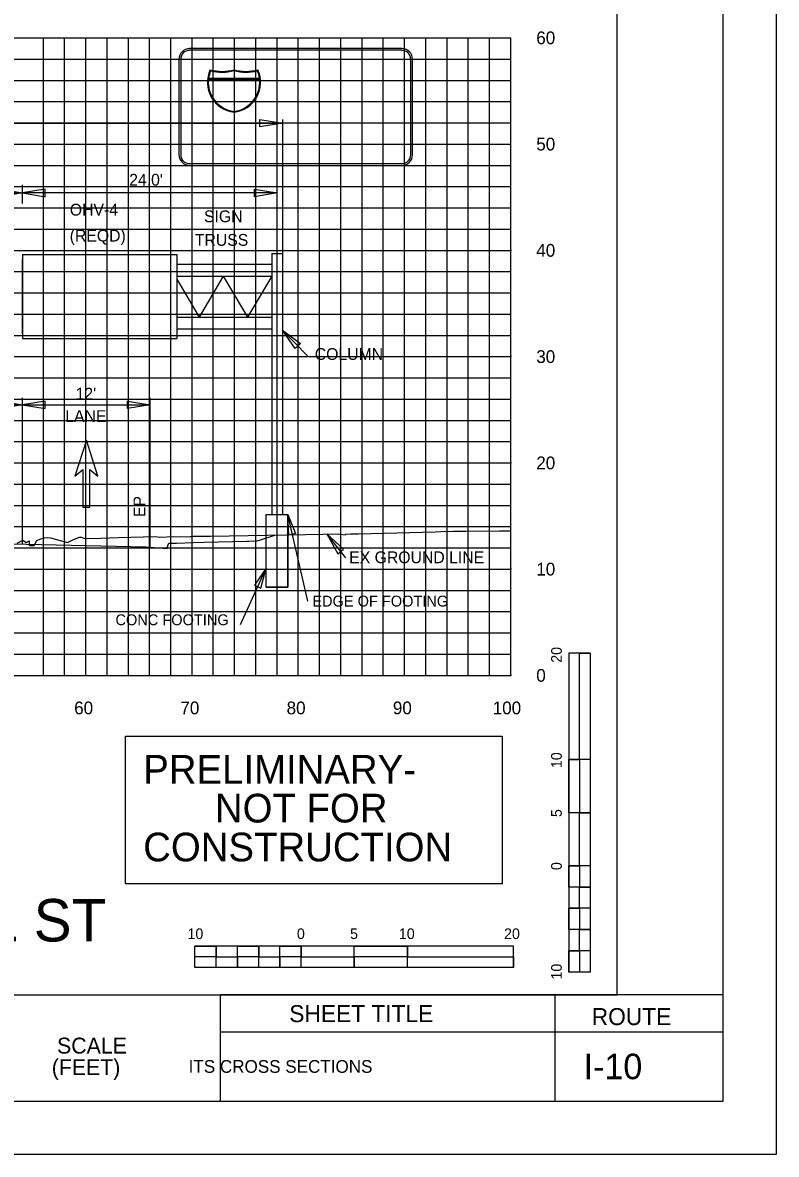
# Model space of a CAD drawing. Extents: x 2193008 to 2198143, y 1236112 to 1237864.
# Drawn here: x 2194781.7 to 2194852.7, y 1237118 to 1237224.5 of the extents above; entities that cross this region are included whole.
import ezdxf

# ---------------------------------------------------------------- set-up
doc = ezdxf.new("R2010")
doc.units = 0
for name, color, linetype in [('1', 7, 'Continuous'), ('10', 7, 'Continuous'), ('3', 7, 'Continuous'), ('31', 7, 'Continuous'), ('60', 7, 'Continuous'), ('ANNO-SHT', 7, 'Continuous'), ('ANNO-SYMB', 7, 'Continuous'), ('ANNO-TXT', 7, 'Continuous'), ('CL-CNST', 7, 'Continuous'), ('GSCOLORFILL', 7, 'Continuous'), ('GSDIMS', 7, 'Continuous'), ('GSOUTLINE', 7, 'Continuous'), ('Level 1', 7, 'Continuous'), ('Level 28', 7, 'Continuous'), ('Level 33', 7, 'Continuous'), ('Level 55', 7, 'Continuous'), ('Level 6', 7, 'Continuous'), ('Level 62', 7, 'Continuous'), ('M-ROADS', 7, 'Continuous'), ('SHT-BDR', 7, 'Continuous'), ('SHT-BNDRY', 7, 'Continuous'), ('V7Level1', 7, 'Continuous')]:
    doc.layers.add(name, color=color, linetype=linetype)

msp = doc.modelspace()

# ---------------------------------------------------------------- linework, layer by layer
msp.add_line((2194805.69, 1237202.24), (2194805.69, 1237208.86))
at = {"layer": '1'}
msp.add_lwpolyline([(2194791.41, 1237157.4), (2194826.87, 1237157.4), (2194826.87, 1237143.51), (2194791.41, 1237143.51)], close=True, dxfattribs=at)
at = {"layer": '3'}
for p, q in [((2194736.69, 1237215.09), (2194806.19, 1237215.09)), ((2194806.19, 1237215.44), (2194806.19, 1237202.8)), ((2194805.19, 1237202.8), (2194805.19, 1237178.26)), ((2194806.19, 1237202.8), (2194806.19, 1237178.26)), ((2194808.56, 1237193.17), (2194806.19, 1237195.61)), ((2194781.74, 1237175.47), (2194781.74, 1237189.23)), ((2194793.74, 1237175.2), (2194793.74, 1237189.23)), ((2194804.66, 1237178.26), (2194806.69, 1237178.26)), ((2194804.66, 1237171.41), (2194804.66, 1237178.26)), ((2194806.69, 1237171.41), (2194806.69, 1237178.26)), ((2194808.58, 1237170.1), (2194806.69, 1237178.26)), ((2194812.15, 1237174.16), (2194810.38, 1237176.42)), ((2194802.24, 1237167.9), (2194804.66, 1237173.2)), ((2194804.66, 1237171.41), (2194806.69, 1237171.41))]:
    msp.add_line(p, q, dxfattribs=at)
at = {"layer": '60'}
for p, q in [((2194827.69, 1237163.11), (2194827.69, 1237223.11)), ((2194827.75, 1237203.11), (2194827.69, 1237203.11)), ((2194827.75, 1237193.11), (2194827.69, 1237193.11)), ((2194827.75, 1237183.11), (2194827.69, 1237183.11)), ((2194827.75, 1237173.11), (2194827.69, 1237173.11)), ((2194697.69, 1237163.11), (2194827.69, 1237163.11)), ((2194787.69, 1237163.05), (2194787.69, 1237163.11)), ((2194797.69, 1237163.05), (2194797.69, 1237163.11)), ((2194807.69, 1237163.05), (2194807.69, 1237163.11)), ((2194817.69, 1237163.05), (2194817.69, 1237163.11)), ((2194827.69, 1237163.05), (2194827.69, 1237163.11)), ((2194827.75, 1237163.11), (2194827.69, 1237163.11))]:
    msp.add_line(p, q, dxfattribs=at)
at = {"layer": 'ANNO-TXT'}
for p, q in [((2194800.35, 1237129.57), (2194831.88, 1237129.57)), ((2194831.88, 1237129.57), (2194847.69, 1237129.57))]:
    msp.add_line(p, q, dxfattribs=at)
at = {"layer": 'CL-CNST'}
msp.add_lwpolyline([(2194755.3, 1237176.05), (2194793.33, 1237175.21), (2194793.73, 1237175.18), (2194795.33, 1237175.05), (2194795.36, 1237175.15), (2194795.5, 1237175.55), (2194795.56, 1237175.55), (2194795.83, 1237175.55), (2194796.23, 1237175.56), (2194797.83, 1237175.63), (2194798.83, 1237175.65), (2194802.83, 1237175.73), (2194803.03, 1237175.73), (2194803.83, 1237175.77), (2194804.12, 1237175.87), (2194805.49, 1237176.32)], dxfattribs=at)
at = {"layer": 'GSCOLORFILL'}
msp.add_line((2194781.74, 1237195.26), (2194781.74, 1237202.25), dxfattribs=at)
at = {"layer": 'GSDIMS'}
for p, q in [((2194769.25, 1237208.51), (2194781.74, 1237208.51)), ((2194781.74, 1237207.53), (2194781.74, 1237209.27)), ((2194805.69, 1237208.51), (2194781.74, 1237208.51)), ((2194781.74, 1237202.71), (2194796.25, 1237202.71)), ((2194781.74, 1237202.71), (2194781.74, 1237194.8)), ((2194796.25, 1237202.71), (2194796.25, 1237194.8)), ((2194805.19, 1237202.8), (2194806.19, 1237202.8)), ((2194796.25, 1237201.8), (2194805.19, 1237201.8)), ((2194796.25, 1237200.69), (2194805.19, 1237200.69)), ((2194796.25, 1237200.39), (2194798.35, 1237196.82)), ((2194800.63, 1237200.69), (2194798.35, 1237196.82)), ((2194800.63, 1237200.69), (2194802.91, 1237196.82)), ((2194805.19, 1237200.69), (2194802.91, 1237196.82)), ((2194796.25, 1237196.82), (2194805.19, 1237196.82)), ((2194796.25, 1237195.71), (2194805.19, 1237195.71)), ((2194781.74, 1237194.8), (2194796.25, 1237194.8)), ((2194769.74, 1237188.57), (2194781.74, 1237188.57)), ((2194781.74, 1237188.57), (2194793.74, 1237188.57))]:
    msp.add_line(p, q, dxfattribs=at)
for points in [[(2194806.19, 1237215.09), (2194804.06, 1237214.75), (2194804.06, 1237215.44)], [(2194781.74, 1237208.51), (2194779.61, 1237208.16), (2194779.61, 1237208.86)], [(2194781.74, 1237208.51), (2194783.87, 1237208.16), (2194783.87, 1237208.86)], [(2194805.69, 1237208.51), (2194803.56, 1237208.16), (2194803.56, 1237208.86)], [(2194806.19, 1237195.61), (2194807.91, 1237194.34), (2194807.4, 1237193.86)], [(2194781.74, 1237188.57), (2194779.61, 1237188.22), (2194779.61, 1237188.91)], [(2194781.74, 1237188.57), (2194783.87, 1237188.22), (2194783.87, 1237188.91)], [(2194793.74, 1237188.57), (2194791.61, 1237188.22), (2194791.61, 1237188.91)], [(2194806.69, 1237178.26), (2194807.43, 1237176.46), (2194806.81, 1237176.32)], [(2194810.38, 1237176.42), (2194811.41, 1237174.54), (2194811.95, 1237174.98)], [(2194804.66, 1237173.2), (2194803.57, 1237171.59), (2194804.16, 1237171.32)]]:
    msp.add_lwpolyline(points, close=True, dxfattribs=at)
at = {"layer": 'GSOUTLINE'}
for p, q in [((2194817.44, 1237222.1), (2194797.45, 1237222.1)), ((2194817.44, 1237221.94), (2194797.45, 1237221.94)), ((2194796.45, 1237221.1), (2194796.45, 1237212.11)), ((2194796.62, 1237221.1), (2194796.62, 1237212.11)), ((2194818.28, 1237212.11), (2194818.28, 1237221.1)), ((2194818.44, 1237212.11), (2194818.44, 1237221.1)), ((2194797.45, 1237211.28), (2194817.44, 1237211.28)), ((2194797.45, 1237211.11), (2194817.44, 1237211.11))]:
    msp.add_line(p, q, dxfattribs=at)
for points in [[(2194799.24, 1237219.19), (2194804.04, 1237219.19)], [(2194804.03, 1237219.28), (2194799.25, 1237219.28)]]:
    msp.add_lwpolyline(points, dxfattribs=at)
for centre, major_axis, start_param, end_param in [((2194797.45, 1237221.1), (1, 0), 1.570796, 3.141593), ((2194797.45, 1237221.1), (0.833, 0), 1.570796, 3.141593), ((2194817.44, 1237221.1), (1, 0), 0, 1.570796), ((2194817.44, 1237221.1), (0.833, 0), 0, 1.570796), ((2194801.97, 1237218.92), (2.83, 0), 2.709569, 4.594469), ((2194800.52, 1237223.95), (4, 0), 4.428637, 4.996141), ((2194802.76, 1237223.95), (4, 0), 4.428637, 4.996141), ((2194801.31, 1237218.92), (2.83, 0), 4.830309, 6.715209), ((2194801.97, 1237218.92), (2.75, 0), 3.043371, 4.590878), ((2194801.97, 1237218.92), (2.75, 0), 2.735396, 3.01287), ((2194800.52, 1237223.95), (4.08, 0), 4.446475, 4.990194), ((2194802.76, 1237223.95), (4.08, 0), 4.434584, 4.978303), ((2194801.31, 1237218.92), (2.75, 0), 4.8339, 6.381407), ((2194801.31, 1237218.92), (2.75, 0), 0.128722, 0.406196), ((2194797.45, 1237212.11), (1, 0), 3.141593, 4.712389), ((2194797.45, 1237212.11), (0.833, 0), 3.141593, 4.712389), ((2194817.44, 1237212.11), (1, 0), 4.712389, 6.283185), ((2194817.44, 1237212.11), (0.833, 0), 4.712389, 6.283185)]:
    msp.add_ellipse(centre, major_axis=major_axis, ratio=0.999829, start_param=start_param, end_param=end_param, dxfattribs=at)
at = {"layer": 'Level 1'}
for p, q in [((2194833.16, 1237165.19), (2194833.16, 1237135.19)), ((2194835.16, 1237165.19), (2194833.16, 1237165.19)), ((2194835.16, 1237165.19), (2194835.16, 1237155.19)), ((2194835.16, 1237165.19), (2194835.16, 1237135.19)), ((2194834.16, 1237155.19), (2194833.16, 1237155.19)), ((2194835.16, 1237155.19), (2194833.16, 1237155.19)), ((2194834.16, 1237155.19), (2194834.16, 1237150.19)), ((2194835.16, 1237150.19), (2194833.16, 1237150.19)), ((2194835.16, 1237150.19), (2194834.16, 1237150.19)), ((2194835.16, 1237150.19), (2194835.16, 1237145.19)), ((2194834.16, 1237145.19), (2194833.16, 1237145.19)), ((2194835.16, 1237145.19), (2194833.16, 1237145.19)), ((2194834.16, 1237145.19), (2194834.16, 1237143.19)), ((2194835.16, 1237143.19), (2194834.16, 1237143.19)), ((2194835.16, 1237143.19), (2194835.16, 1237141.19)), ((2194834.16, 1237141.19), (2194833.16, 1237141.19)), ((2194834.16, 1237141.19), (2194834.16, 1237139.19)), ((2194835.16, 1237139.19), (2194834.16, 1237139.19)), ((2194835.16, 1237139.19), (2194835.16, 1237137.19)), ((2194827.96, 1237137.63), (2194797.96, 1237137.63)), ((2194797.96, 1237135.63), (2194797.96, 1237137.63)), ((2194799.96, 1237136.63), (2194799.96, 1237137.63)), ((2194803.96, 1237136.63), (2194803.96, 1237137.63)), ((2194807.96, 1237136.63), (2194807.96, 1237137.63)), ((2194807.96, 1237135.63), (2194807.96, 1237137.63)), ((2194812.96, 1237135.63), (2194812.96, 1237137.63)), ((2194817.96, 1237136.63), (2194817.96, 1237137.63)), ((2194817.96, 1237135.63), (2194817.96, 1237137.63)), ((2194827.96, 1237135.63), (2194827.96, 1237137.63)), ((2194834.16, 1237137.19), (2194833.16, 1237137.19)), ((2194834.16, 1237137.19), (2194834.16, 1237135.19)), ((2194799.96, 1237136.63), (2194797.96, 1237136.63)), ((2194801.96, 1237135.63), (2194801.96, 1237136.63)), ((2194803.96, 1237136.63), (2194801.96, 1237136.63)), ((2194805.96, 1237135.63), (2194805.96, 1237136.63)), ((2194807.96, 1237136.63), (2194805.96, 1237136.63)), ((2194812.96, 1237135.63), (2194812.96, 1237136.63)), ((2194817.96, 1237136.63), (2194812.96, 1237136.63)), ((2194827.96, 1237135.63), (2194797.96, 1237135.63)), ((2194801.96, 1237135.63), (2194799.96, 1237135.63)), ((2194805.96, 1237135.63), (2194803.96, 1237135.63)), ((2194812.96, 1237135.63), (2194807.96, 1237135.63)), ((2194827.96, 1237135.63), (2194817.96, 1237135.63)), ((2194835.16, 1237135.19), (2194833.16, 1237135.19))]:
    msp.add_line(p, q, dxfattribs=at)
for points in [[(2194834.16, 1237155.19), (2194834.16, 1237165.19), (2194835.16, 1237165.19), (2194835.16, 1237155.19)], [(2194833.16, 1237150.19), (2194833.16, 1237155.19), (2194834.16, 1237155.19), (2194834.16, 1237150.19)], [(2194834.16, 1237145.19), (2194834.16, 1237150.19), (2194835.16, 1237150.19), (2194835.16, 1237145.19)], [(2194833.16, 1237143.19), (2194833.16, 1237145.19), (2194834.16, 1237145.19), (2194834.16, 1237143.19)], [(2194834.16, 1237141.19), (2194834.16, 1237143.19), (2194835.16, 1237143.19), (2194835.16, 1237141.19)], [(2194833.16, 1237139.19), (2194833.16, 1237141.19), (2194834.16, 1237141.19), (2194834.16, 1237139.19)], [(2194834.16, 1237137.19), (2194834.16, 1237139.19), (2194835.16, 1237139.19), (2194835.16, 1237137.19)], [(2194797.96, 1237137.63), (2194799.96, 1237137.63), (2194799.96, 1237136.63), (2194797.96, 1237136.63)], [(2194801.96, 1237137.63), (2194803.96, 1237137.63), (2194803.96, 1237136.63), (2194801.96, 1237136.63)], [(2194805.96, 1237137.63), (2194807.96, 1237137.63), (2194807.96, 1237136.63), (2194805.96, 1237136.63)], [(2194812.96, 1237137.63), (2194817.96, 1237137.63), (2194817.96, 1237136.63), (2194812.96, 1237136.63)], [(2194833.16, 1237135.19), (2194833.16, 1237137.19), (2194834.16, 1237137.19), (2194834.16, 1237135.19)], [(2194799.96, 1237136.63), (2194801.96, 1237136.63), (2194801.96, 1237135.63), (2194799.96, 1237135.63)], [(2194803.96, 1237136.63), (2194805.96, 1237136.63), (2194805.96, 1237135.63), (2194803.96, 1237135.63)], [(2194807.96, 1237136.63), (2194812.96, 1237136.63), (2194812.96, 1237135.63), (2194807.96, 1237135.63)], [(2194817.96, 1237136.63), (2194827.96, 1237136.63), (2194827.96, 1237135.63), (2194817.96, 1237135.63)]]:
    msp.add_lwpolyline(points, close=True, dxfattribs=at)
at = {"layer": 'Level 28'}
for p, q in [((2194787.74, 1237185.26), (2194786.65, 1237181.86)), ((2194788.83, 1237181.86), (2194787.74, 1237185.26)), ((2194786.65, 1237181.86), (2194787.41, 1237182.5)), ((2194787.41, 1237182.5), (2194787.41, 1237178.93)), ((2194788.07, 1237178.93), (2194788.07, 1237182.5)), ((2194788.07, 1237182.5), (2194788.83, 1237181.86)), ((2194787.41, 1237178.93), (2194788.07, 1237178.93))]:
    msp.add_line(p, q, dxfattribs=at)
at = {"layer": 'Level 6'}
msp.add_line((2194847.69, 1237133.05), (2194800.35, 1237133.05), dxfattribs=at)
at = {"layer": 'Level 62'}
for p, q in [((2194697.69, 1237223.11), (2194827.69, 1237223.11)), ((2194783.69, 1237163.11), (2194783.69, 1237223.11)), ((2194785.69, 1237163.11), (2194785.69, 1237223.11)), ((2194787.69, 1237163.11), (2194787.69, 1237223.11)), ((2194789.69, 1237163.11), (2194789.69, 1237223.11)), ((2194791.69, 1237163.11), (2194791.69, 1237223.11)), ((2194793.69, 1237163.11), (2194793.69, 1237223.11)), ((2194795.69, 1237163.11), (2194795.69, 1237223.11)), ((2194797.69, 1237163.11), (2194797.69, 1237223.11)), ((2194799.69, 1237163.11), (2194799.69, 1237223.11)), ((2194801.69, 1237163.11), (2194801.69, 1237223.11)), ((2194803.69, 1237163.11), (2194803.69, 1237223.11)), ((2194805.69, 1237163.11), (2194805.69, 1237223.11)), ((2194807.69, 1237163.11), (2194807.69, 1237223.11)), ((2194809.69, 1237163.11), (2194809.69, 1237223.11)), ((2194811.69, 1237163.11), (2194811.69, 1237223.11)), ((2194813.69, 1237163.11), (2194813.69, 1237223.11)), ((2194815.69, 1237163.11), (2194815.69, 1237223.11)), ((2194817.69, 1237163.11), (2194817.69, 1237223.11)), ((2194819.69, 1237163.11), (2194819.69, 1237223.11)), ((2194821.69, 1237163.11), (2194821.69, 1237223.11)), ((2194823.69, 1237163.11), (2194823.69, 1237223.11)), ((2194825.69, 1237163.11), (2194825.69, 1237223.11)), ((2194827.69, 1237163.11), (2194827.69, 1237223.11)), ((2194697.69, 1237221.11), (2194827.69, 1237221.11)), ((2194697.69, 1237219.11), (2194827.69, 1237219.11)), ((2194697.69, 1237217.11), (2194827.69, 1237217.11)), ((2194697.69, 1237215.11), (2194827.69, 1237215.11)), ((2194697.69, 1237213.11), (2194827.69, 1237213.11)), ((2194697.69, 1237211.11), (2194827.69, 1237211.11)), ((2194697.69, 1237209.11), (2194827.69, 1237209.11)), ((2194697.69, 1237207.11), (2194827.69, 1237207.11)), ((2194697.69, 1237205.11), (2194827.69, 1237205.11)), ((2194697.69, 1237203.11), (2194827.69, 1237203.11)), ((2194697.69, 1237201.11), (2194827.69, 1237201.11)), ((2194697.69, 1237199.11), (2194827.69, 1237199.11)), ((2194697.69, 1237197.11), (2194827.69, 1237197.11)), ((2194697.69, 1237195.11), (2194827.69, 1237195.11)), ((2194697.69, 1237193.11), (2194827.69, 1237193.11)), ((2194697.69, 1237191.11), (2194827.69, 1237191.11)), ((2194697.69, 1237189.11), (2194827.69, 1237189.11)), ((2194697.69, 1237187.11), (2194827.69, 1237187.11)), ((2194697.69, 1237185.11), (2194827.69, 1237185.11)), ((2194697.69, 1237183.11), (2194827.69, 1237183.11)), ((2194697.69, 1237181.11), (2194827.69, 1237181.11)), ((2194697.69, 1237179.11), (2194827.69, 1237179.11)), ((2194697.69, 1237177.11), (2194827.69, 1237177.11)), ((2194697.69, 1237175.11), (2194827.69, 1237175.11)), ((2194697.69, 1237173.11), (2194827.69, 1237173.11)), ((2194697.69, 1237171.11), (2194827.69, 1237171.11)), ((2194697.69, 1237169.11), (2194827.69, 1237169.11)), ((2194697.69, 1237167.11), (2194827.69, 1237167.11)), ((2194697.69, 1237165.11), (2194827.69, 1237165.11)), ((2194697.69, 1237163.11), (2194827.69, 1237163.11))]:
    msp.add_line(p, q, dxfattribs=at)
msp.add_lwpolyline([(2194512.69, 1237118.04), (2194852.69, 1237118.04), (2194852.69, 1237338.04), (2194512.69, 1237338.04)], close=True, dxfattribs=at)
at = {"layer": 'M-ROADS'}
msp.add_lwpolyline([(2194781.22, 1237175.57), (2194781.76, 1237175.83), (2194782.06, 1237175.63), (2194782.37, 1237175.78), (2194782.37, 1237175.36), (2194782.41, 1237175.31), (2194782.46, 1237175.33), (2194782.53, 1237175.35), (2194782.83, 1237175.32), (2194783.08, 1237175.79), (2194783.15, 1237175.84), (2194783.3, 1237175.89), (2194783.46, 1237175.97), (2194783.81, 1237176.07), (2194784.07, 1237176.09), (2194784.37, 1237176.05), (2194784.93, 1237175.9), (2194785.97, 1237175.61), (2194786.52, 1237175.91), (2194787.1, 1237176.13), (2194787.17, 1237176.13), (2194787.24, 1237176.13), (2194787.58, 1237175.99), (2194789.1, 1237176.01), (2194790.72, 1237176.09), (2194794.27, 1237176.18), (2194794.61, 1237176.11), (2194795.97, 1237176.18), (2194797.52, 1237176.15), (2194797.55, 1237176.17), (2194797.8, 1237176.21), (2194799.38, 1237176.21), (2194808.38, 1237176.37), (2194810.01, 1237176.41), (2194811.48, 1237176.42), (2194812.1, 1237176.34), (2194812.17, 1237176.39), (2194812.59, 1237176.43), (2194813.34, 1237176.43), (2194820.56, 1237176.63), (2194821.69, 1237176.69), (2194821.71, 1237176.65), (2194822.29, 1237176.68), (2194823.47, 1237176.69), (2194826.62, 1237176.72), (2194827.69, 1237176.71)], dxfattribs=at)
at = {"layer": 'SHT-BDR'}
msp.add_lwpolyline([(2194537.69, 1237133.05), (2194837.69, 1237133.05), (2194837.69, 1237323.05), (2194537.69, 1237323.05)], close=True, dxfattribs=at)
at = {"layer": 'SHT-BNDRY'}
for p, q in [((2194800.35, 1237123.04), (2194800.35, 1237133.05)), ((2194831.88, 1237123.04), (2194831.88, 1237133.05))]:
    msp.add_line(p, q, dxfattribs=at)
msp.add_lwpolyline([(2194525.19, 1237123.04), (2194847.69, 1237123.04), (2194847.69, 1237333.04), (2194525.19, 1237333.04)], close=True, dxfattribs=at)
at = {"layer": 'V7Level1'}
msp.add_lwpolyline([(2194806.69, 1237171.41), (2194804.66, 1237171.41), (2194804.66, 1237178.26), (2194806.69, 1237178.26)], close=True, dxfattribs=at)

# ---------------------------------------------------------------- texts
at = {"layer": '1'}
for s, p in [('PRELIMINARY-', (2194793.09, 1237152.92)), ('NOT FOR', (2194799.84, 1237149.27)), ('CONSTRUCTION', (2194793.09, 1237145.61))]:
    msp.add_text(s, height=2.7, dxfattribs=at).set_placement(p)
at = {"layer": '10'}
for s, p in [('60', (2194786.59, 1237159.45)), ('70', (2194796.59, 1237159.45)), ('80', (2194806.59, 1237159.45)), ('90', (2194816.59, 1237159.45)), ('100', (2194825.99, 1237159.45))]:
    msp.add_text(s, height=1.2, dxfattribs=at).set_placement(p)
at = {"layer": '31'}
for s, p in [('60', (2194830.09, 1237222.51)), ('50', (2194830.09, 1237212.51)), ('40', (2194830.09, 1237202.51)), ('30', (2194830.09, 1237192.51)), ('20', (2194830.09, 1237182.51)), ('10', (2194830.09, 1237172.51)), ('0', (2194830.09, 1237162.51))]:
    msp.add_text(s, height=1.2, dxfattribs=at).set_placement(p)
at = {"layer": 'ANNO-SHT'}
for s, height, p in [(' I-10 ', 2.4, (2194833.65, 1237125.11)), ('          ITS CROSS SECTIONS          ', 1.2, (2194792.91, 1237125.71))]:
    msp.add_text(s, height=height, rotation=360, dxfattribs=at).set_placement(p)
at = {"layer": 'ANNO-SYMB'}
for s, p in [('SCALE', (2194784.98, 1237127.52)), ('(FEET)', (2194784.48, 1237125.49))]:
    msp.add_text(s, height=1.499, rotation=0.0572, dxfattribs=at).set_placement(p)
at = {"layer": 'ANNO-TXT'}
for s, p in [('SHEET TITLE', (2194806.84, 1237130.48)), ('ROUTE', (2194835.31, 1237130.2))]:
    msp.add_text(s, height=1.6, dxfattribs=at).set_placement(p)
at = {"layer": 'Level 1'}
for s, height, rotation, p in [('20', 0.999, 90.0572, (2194832.49, 1237164.3)), ('10', 0.999, 90.0572, (2194832.49, 1237154.39)), ('5', 1, 90.0572, (2194832.49, 1237149.78)), ('0', 1, 90.0572, (2194832.49, 1237144.79)), ('10', 0.999, 0.0572, (2194797.26, 1237138.3)), ('0', 1, 0.0572, (2194807.56, 1237138.3)), ('5', 0.999, 0.0572, (2194812.56, 1237138.3)), ('10', 0.999, 0.0572, (2194817.16, 1237138.3)), ('20', 0.999, 0.0572, (2194827.06, 1237138.3)), ('10', 0.999, 90.0572, (2194832.49, 1237134.49))]:
    msp.add_text(s, height=height, rotation=rotation, dxfattribs=at).set_placement(p)
at = {"layer": 'Level 33'}
msp.add_text('CANAL ST', height=3.998, rotation=360, dxfattribs=at).set_placement((2194763.47, 1237138.07))
at = {"layer": 'Level 55'}
for s, height, p in [("24.0'", 1.11, (2194791.77, 1237209.2)), ('SIGN', 1.11, (2194798.81, 1237205.76)), ('TRUSS', 1.11, (2194797.95, 1237203.54)), ('COLUMN', 1.11, (2194809.24, 1237192.8)), ("12'", 1.11, (2194786.72, 1237189.07)), ('LANE', 1.11, (2194785.75, 1237186.96)), ('EX GROUND LINE', 1.1105, (2194812.48, 1237173.67)), ('EDGE OF FOOTING', 1.0246, (2194809.01, 1237169.59)), ('CONC FOOTING', 1.0246, (2194790.48, 1237167.83))]:
    msp.add_text(s, height=height, dxfattribs=at).set_placement(p)
for s, rotation, p in [('OHV-4', 360, (2194786.18, 1237206.38)), ('(REQD)', 360, (2194786.17, 1237203.94)), ('EP', 90, (2194793.29, 1237178.01))]:
    msp.add_text(s, height=1.11, rotation=rotation, dxfattribs=at).set_placement(p)

doc.saveas('drawing.dxf')
